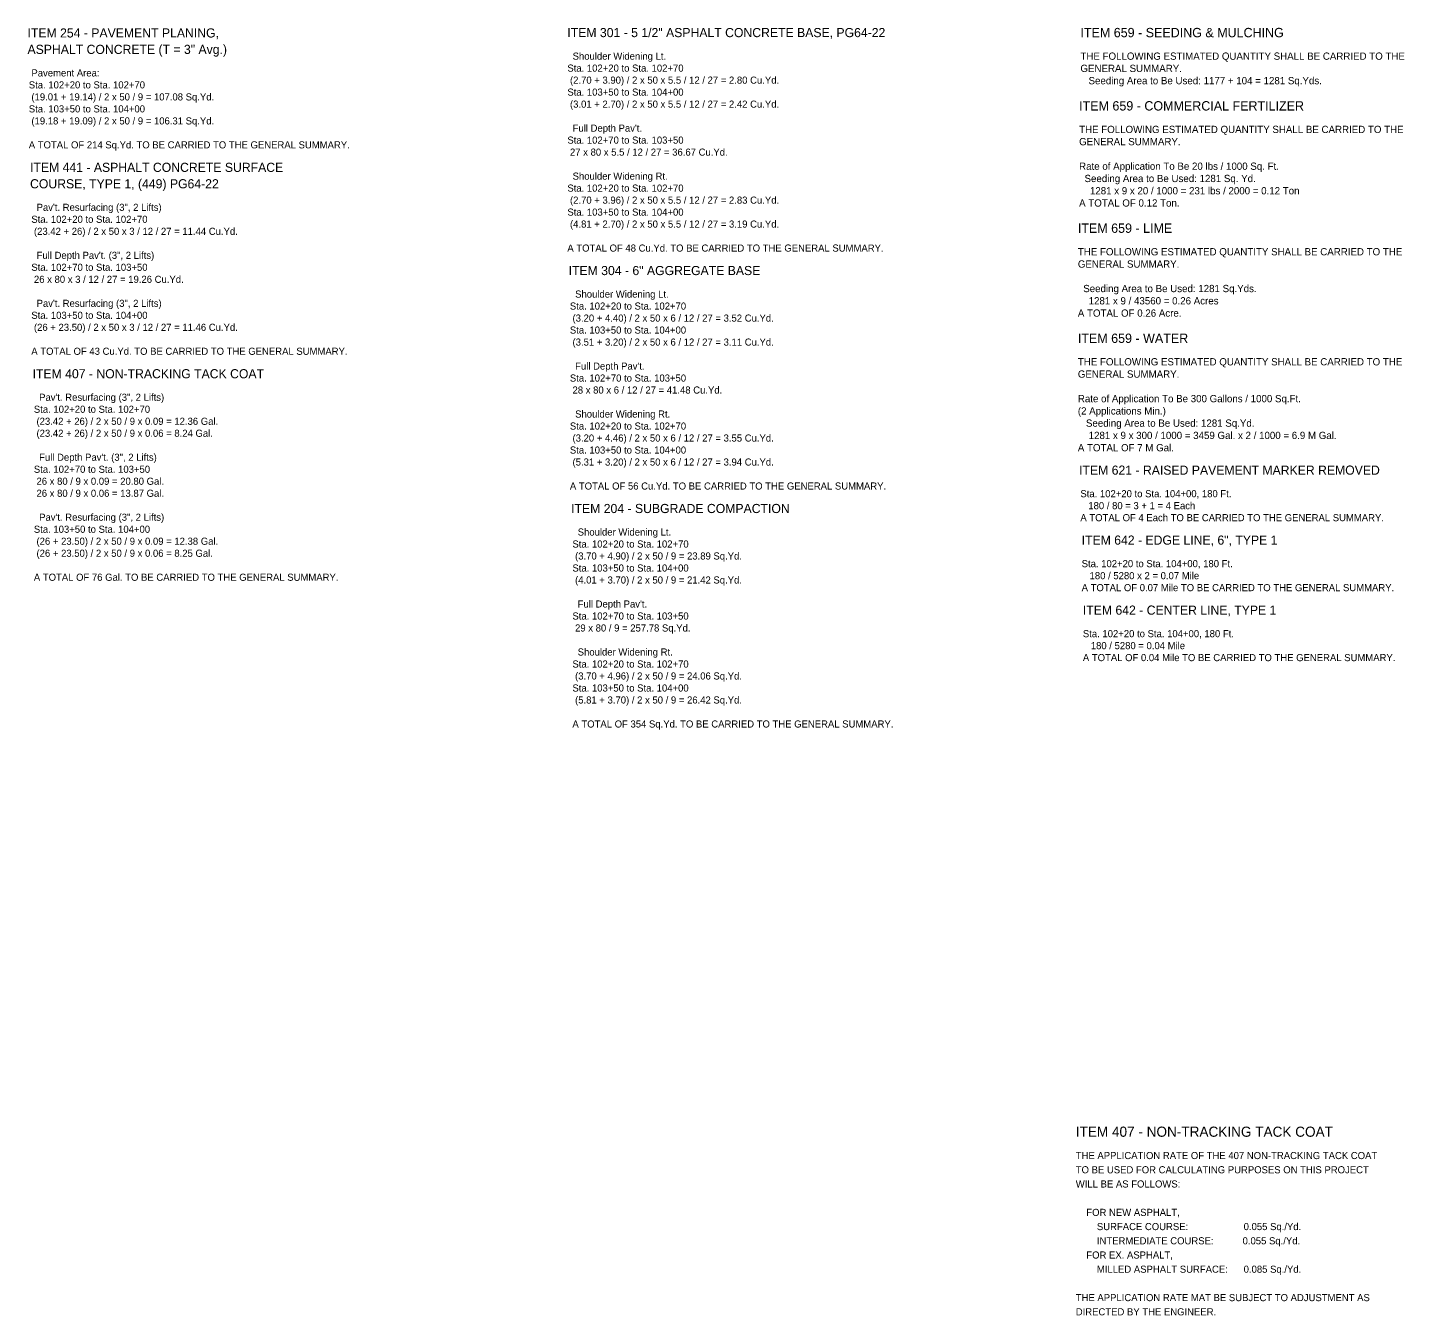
# Model space of a CAD drawing. Extents: x -40.7 to 43.6, y -9.8 to 57.4.
# Drawn here: x 3.06 to 30.19, y 23.95 to 49.33 of the extents above; entities that cross this region are included whole.
import ezdxf

# ---------------------------------------------------------------- set-up
doc = ezdxf.new("R2010")
doc.units = 0
doc.layers.add('Default', color=7, linetype='Continuous')
doc.layers.add('SH_Text', color=7, linetype='Continuous')

msp = doc.modelspace()

# ---------------------------------------------------------------- texts
at = {"layer": 'Default'}
for s, height, p in [('ITEM 254 - PAVEMENT PLANING,', 0.18, (3.058, 49.136)), ('ITEM 301 - 5 1/2" ASPHALT CONCRETE BASE, PG64-22', 0.18, (13.695, 49.143)), ('ITEM 659 - SEEDING & MULCHING', 0.18406, (23.805, 49.141)), ('ASPHALT CONCRETE (T = 3" Avg.)', 0.18, (3.058, 48.812)), ('  Shoulder Widening Lt.', 0.14, (13.695, 48.699)), ('THE FOLLOWING ESTIMATED QUANTITY SHALL BE CARRIED TO THE', 0.14317, (23.805, 48.697)), ('Sta. 102+20 to Sta. 102+70', 0.14, (13.695, 48.463)), ('GENERAL SUMMARY.', 0.14317, (23.805, 48.456)), (' Pavement Area:', 0.14, (3.083, 48.368)), (' (2.70 + 3.90) / 2 x 50 x 5.5 / 12 / 27 = 2.80 Cu.Yd.', 0.14, (13.695, 48.226)), ('   Seeding Area to Be Used: 1177 + 104 = 1281 Sq.Yds.', 0.14317, (23.805, 48.214)), ('Sta. 102+20 to Sta. 102+70', 0.14, (3.083, 48.132)), (' (19.01 + 19.14) / 2 x 50 / 9 = 107.08 Sq.Yd.', 0.14, (3.083, 47.895)), ('Sta. 103+50 to Sta. 104+00', 0.14, (13.695, 47.99)), ('Sta. 103+50 to Sta. 104+00', 0.14, (3.083, 47.659)), (' (3.01 + 2.70) / 2 x 50 x 5.5 / 12 / 27 = 2.42 Cu.Yd.', 0.14, (13.695, 47.753)), ('ITEM 659 - COMMERCIAL FERTILIZER', 0.18406, (23.779, 47.697)), (' (19.18 + 19.09) / 2 x 50 / 9 = 106.31 Sq.Yd.', 0.14, (3.083, 47.422)), ("  Full Depth Pav't.", 0.14, (13.695, 47.28)), ('THE FOLLOWING ESTIMATED QUANTITY SHALL BE CARRIED TO THE', 0.14317, (23.779, 47.253)), ('A TOTAL OF 214 Sq.Yd. TO BE CARRIED TO THE GENERAL SUMMARY.', 0.14, (3.083, 46.95)), ('Sta. 102+70 to Sta. 103+50', 0.14, (13.695, 47.044)), (' 27 x 80 x 5.5 / 12 / 27 = 36.67 Cu.Yd.', 0.14, (13.695, 46.807)), ('GENERAL SUMMARY.', 0.14317, (23.779, 47.012)), ('ITEM 441 - ASPHALT CONCRETE SURFACE', 0.18, (3.108, 46.487)), ('Rate of Application To Be 20 lbs / 1000 Sq. Ft.', 0.14317, (23.779, 46.528)), ('  Shoulder Widening Rt.', 0.14, (13.695, 46.334)), ('  Seeding Area to Be Used: 1281 Sq. Yd.', 0.14317, (23.779, 46.286)), ('COURSE, TYPE 1, (449) PG64-22', 0.18, (3.108, 46.163)), ('Sta. 102+20 to Sta. 102+70', 0.14, (13.695, 46.098)), ('    1281 x 9 x 20 / 1000 = 231 lbs / 2000 = 0.12 Ton', 0.14317, (23.779, 46.044)), ('  Pav\'t. Resurfacing (3", 2 Lifts)', 0.14, (3.133, 45.719)), (' (2.70 + 3.96) / 2 x 50 x 5.5 / 12 / 27 = 2.83 Cu.Yd.', 0.14, (13.695, 45.861)), ('A TOTAL OF 0.12 Ton.', 0.14317, (23.779, 45.803)), ('Sta. 102+20 to Sta. 102+70', 0.14, (3.133, 45.483)), ('Sta. 103+50 to Sta. 104+00', 0.14, (13.695, 45.625)), (' (23.42 + 26) / 2 x 50 x 3 / 12 / 27 = 11.44 Cu.Yd.', 0.14, (3.133, 45.246)), (' (4.81 + 2.70) / 2 x 50 x 5.5 / 12 / 27 = 3.19 Cu.Yd.', 0.14, (13.695, 45.389)), ('ITEM 659 - LIME', 0.18406, (23.754, 45.286)), ('A TOTAL OF 48 Cu.Yd. TO BE CARRIED TO THE GENERAL SUMMARY.', 0.14, (13.695, 44.916)), ('  Full Depth Pav\'t. (3", 2 Lifts)', 0.14, (3.133, 44.773)), ('THE FOLLOWING ESTIMATED QUANTITY SHALL BE CARRIED TO THE', 0.14317, (23.754, 44.842)), ('Sta. 102+70 to Sta. 103+50', 0.14, (3.133, 44.537)), ('ITEM 304 - 6" AGGREGATE BASE', 0.18, (13.72, 44.453)), ('GENERAL SUMMARY.', 0.14317, (23.754, 44.6)), (' 26 x 80 x 3 / 12 / 27 = 19.26 Cu.Yd.', 0.14, (3.133, 44.3)), ('  Seeding Area to Be Used: 1281 Sq.Yds.', 0.14317, (23.754, 44.117)), ('  Pav\'t. Resurfacing (3", 2 Lifts)', 0.14, (3.133, 43.827)), ('  Shoulder Widening Lt.', 0.14, (13.745, 44.009)), ('    1281 x 9 / 43560 = 0.26 Acres', 0.14317, (23.754, 43.875)), ('Sta. 103+50 to Sta. 104+00', 0.14, (3.133, 43.591)), ('Sta. 102+20 to Sta. 102+70', 0.14, (13.745, 43.773)), (' (3.20 + 4.40) / 2 x 50 x 6 / 12 / 27 = 3.52 Cu.Yd.', 0.14, (13.745, 43.536)), ('A TOTAL OF 0.26 Acre.', 0.14317, (23.754, 43.633)), (' (26 + 23.50) / 2 x 50 x 3 / 12 / 27 = 11.46 Cu.Yd.', 0.14, (3.133, 43.354)), ('Sta. 103+50 to Sta. 104+00', 0.14, (13.745, 43.3)), (' (3.51 + 3.20) / 2 x 50 x 6 / 12 / 27 = 3.11 Cu.Yd.', 0.14, (13.745, 43.063)), ('ITEM 659 - WATER', 0.18406, (23.754, 43.116)), ('A TOTAL OF 43 Cu.Yd. TO BE CARRIED TO THE GENERAL SUMMARY.', 0.14, (3.133, 42.882)), ('ITEM 407 - NON-TRACKING TACK COAT', 0.18, (3.158, 42.419)), ("  Full Depth Pav't.", 0.14, (13.745, 42.59)), ('THE FOLLOWING ESTIMATED QUANTITY SHALL BE CARRIED TO THE', 0.14317, (23.754, 42.673)), ('Sta. 102+70 to Sta. 103+50', 0.14, (13.745, 42.354)), ('GENERAL SUMMARY.', 0.14317, (23.754, 42.431)), ('  Pav\'t. Resurfacing (3", 2 Lifts)', 0.14, (3.183, 41.975)), (' 28 x 80 x 6 / 12 / 27 = 41.48 Cu.Yd.', 0.14, (13.745, 42.118)), ('Rate of Application To Be 300 Gallons / 1000 Sq.Ft.', 0.14317, (23.754, 41.947)), ('Sta. 102+20 to Sta. 102+70', 0.14, (3.183, 41.739)), ('  Shoulder Widening Rt.', 0.14, (13.745, 41.645)), ('(2 Applications Min.)', 0.14317, (23.754, 41.705)), (' (23.42 + 26) / 2 x 50 / 9 x 0.09 = 12.36 Gal.', 0.14, (3.183, 41.502)), ('Sta. 102+20 to Sta. 102+70', 0.14, (13.745, 41.408)), ('   Seeding Area to Be Used: 1281 Sq.Yd.', 0.14317, (23.754, 41.464)), (' (23.42 + 26) / 2 x 50 / 9 x 0.06 = 8.24 Gal.', 0.14, (3.183, 41.266)), (' (3.20 + 4.46) / 2 x 50 x 6 / 12 / 27 = 3.55 Cu.Yd.', 0.14, (13.745, 41.172)), ('    1281 x 9 x 300 / 1000 = 3459 Gal. x 2 / 1000 = 6.9 M Gal.', 0.14317, (23.754, 41.222)), ('Sta. 103+50 to Sta. 104+00', 0.14, (13.745, 40.935)), ('A TOTAL OF 7 M Gal.', 0.14317, (23.754, 40.98)), ('Sta. 102+70 to Sta. 103+50', 0.14, (3.183, 40.556)), ('  Full Depth Pav\'t. (3", 2 Lifts)', 0.14, (3.183, 40.793)), (' (5.31 + 3.20) / 2 x 50 x 6 / 12 / 27 = 3.94 Cu.Yd.', 0.14, (13.745, 40.699)), ('ITEM 621 - RAISED PAVEMENT MARKER REMOVED', 0.18, (23.779, 40.519)), (' 26 x 80 / 9 x 0.09 = 20.80 Gal.', 0.14, (3.183, 40.32)), (' 26 x 80 / 9 x 0.06 = 13.87 Gal.', 0.14, (3.183, 40.083)), ('A TOTAL OF 56 Cu.Yd. TO BE CARRIED TO THE GENERAL SUMMARY.', 0.14, (13.745, 40.226)), ('Sta. 102+20 to Sta. 104+00, 180 Ft.', 0.14, (23.804, 40.075)), ('ITEM 204 - SUBGRADE COMPACTION', 0.18, (13.77, 39.763)), ('   180 / 80 = 3 + 1 = 4 Each', 0.14, (23.804, 39.839)), ('  Pav\'t. Resurfacing (3", 2 Lifts)', 0.14, (3.183, 39.611)), ('A TOTAL OF 4 Each TO BE CARRIED TO THE GENERAL SUMMARY.', 0.14, (23.804, 39.602)), ('Sta. 103+50 to Sta. 104+00', 0.14, (3.183, 39.374)), ('  Shoulder Widening Lt.', 0.14, (13.795, 39.319)), (' (26 + 23.50) / 2 x 50 / 9 x 0.09 = 12.38 Gal.', 0.14, (3.183, 39.138)), ('Sta. 102+20 to Sta. 102+70', 0.14, (13.795, 39.083)), ('ITEM 642 - EDGE LINE, 6", TYPE 1', 0.18, (23.829, 39.14)), (' (26 + 23.50) / 2 x 50 / 9 x 0.06 = 8.25 Gal.', 0.14, (3.183, 38.901)), (' (3.70 + 4.90) / 2 x 50 / 9 = 23.89 Sq.Yd.', 0.14, (13.795, 38.847)), ('Sta. 102+20 to Sta. 104+00, 180 Ft.', 0.14, (23.829, 38.696)), ('A TOTAL OF 76 Gal. TO BE CARRIED TO THE GENERAL SUMMARY.', 0.14, (3.183, 38.428)), ('Sta. 103+50 to Sta. 104+00', 0.14, (13.795, 38.61)), ('   180 / 5280 x 2 = 0.07 Mile', 0.14, (23.829, 38.459)), (' (4.01 + 3.70) / 2 x 50 / 9 = 21.42 Sq.Yd.', 0.14, (13.795, 38.374)), ('A TOTAL OF 0.07 Mile TO BE CARRIED TO THE GENERAL SUMMARY.', 0.14, (23.829, 38.223)), ("  Full Depth Pav't.", 0.14, (13.795, 37.901)), ('Sta. 102+70 to Sta. 103+50', 0.14, (13.795, 37.664)), ('ITEM 642 - CENTER LINE, TYPE 1', 0.18, (23.853, 37.76)), (' 29 x 80 / 9 = 257.78 Sq.Yd.', 0.14, (13.795, 37.428)), ('Sta. 102+20 to Sta. 104+00, 180 Ft.', 0.14, (23.853, 37.316)), ('   180 / 5280 = 0.04 Mile', 0.14, (23.853, 37.08)), ('  Shoulder Widening Rt.', 0.14, (13.795, 36.955)), ('A TOTAL OF 0.04 Mile TO BE CARRIED TO THE GENERAL SUMMARY.', 0.14, (23.853, 36.844)), ('Sta. 102+20 to Sta. 102+70', 0.14, (13.795, 36.718)), (' (3.70 + 4.96) / 2 x 50 / 9 = 24.06 Sq.Yd.', 0.14, (13.795, 36.482)), ('Sta. 103+50 to Sta. 104+00', 0.14, (13.795, 36.245)), (' (5.81 + 3.70) / 2 x 50 / 9 = 26.42 Sq.Yd.', 0.14, (13.795, 36.009)), ('A TOTAL OF 354 Sq.Yd. TO BE CARRIED TO THE GENERAL SUMMARY.', 0.14, (13.795, 35.536)), ('ITEM 407 - NON-TRACKING TACK COAT', 0.2, (23.713, 27.47))]:
    msp.add_text(s, height=height, dxfattribs=at).set_placement(p)
at = {"layer": 'SH_Text'}
for s, p in [('THE APPLICATION RATE OF THE 407 NON-TRACKING TACK COAT', (23.713, 27.03)), ('TO BE USED FOR CALCULATING PURPOSES ON THIS PROJECT', (23.713, 26.75)), ('WILL BE AS FOLLOWS:', (23.713, 26.47)), ('    FOR NEW ASPHALT,', (23.713, 25.91)), ('        SURFACE COURSE:                     0.055 Sq./Yd.', (23.713, 25.63)), ('        INTERMEDIATE COURSE:           0.055 Sq./Yd.', (23.713, 25.35)), ('    FOR EX. ASPHALT,', (23.713, 25.07)), ('        MILLED ASPHALT SURFACE:      0.085 Sq./Yd.', (23.713, 24.79)), ('THE APPLICATION RATE MAT BE SUBJECT TO ADJUSTMENT AS', (23.713, 24.23)), ('DIRECTED BY THE ENGINEER.', (23.713, 23.95))]:
    msp.add_text(s, height=0.14, dxfattribs=at).set_placement(p)

doc.saveas('drawing.dxf')
